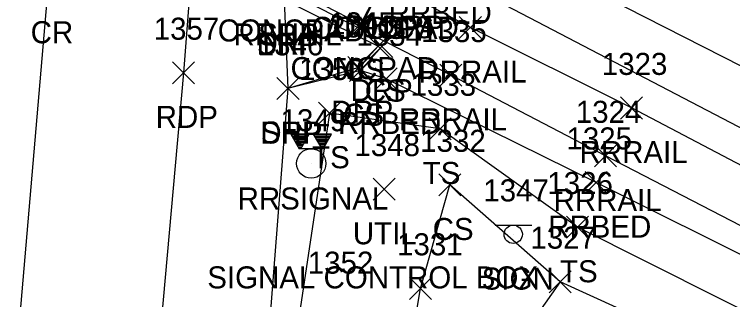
# Model space of a CAD drawing. Extents: x 1443960 to 1446865, y 610387 to 616706.
# Drawn here: x 1446594.4 to 1446659.6, y 611104.4 to 611130.2 of the extents above; entities that cross this region are included whole.
import ezdxf

# ---------------------------------------------------------------- set-up
doc = ezdxf.new("R2010")
doc.units = 0
for name, color, linetype in [('L_A', 7, 'Continuous'), ('L_I', 7, 'Continuous'), ('L_TIC', 7, 'Continuous'), ('LELB', 7, 'Continuous'), ('LS', 7, 'Continuous'), ('P_A', 7, 'Continuous'), ('P_I', 7, 'Continuous'), ('P_TIC', 7, 'Continuous'), ('PET', 7, 'Continuous'), ('PRC', 7, 'Continuous'), ('PSP', 7, 'Continuous'), ('R_A', 7, 'Continuous'), ('R_I', 7, 'Continuous'), ('R_TIC', 7, 'Continuous'), ('RDP', 7, 'Continuous'), ('RR', 7, 'Continuous'), ('RRB', 7, 'Continuous'), ('S_A', 7, 'Continuous'), ('S_I', 7, 'Continuous'), ('SSGN', 7, 'Continuous'), ('TCSH', 7, 'Continuous'), ('U_A', 7, 'Continuous'), ('U_C', 7, 'Continuous'), ('U_I', 7, 'Continuous'), ('UDEFAULT', 7, 'Continuous')]:
    doc.layers.add(name, color=color, linetype=linetype)

msp = doc.modelspace()

# ---------------------------------------------------------------- linework, layer by layer
at = {"layer": 'L_TIC'}
for points in [[(1446624.86, 611128.366), (1446626.86, 611130.366)], [(1446626.86, 611128.366), (1446624.86, 611130.366)], [(1446624.927, 611128.189), (1446626.927, 611130.189)], [(1446626.927, 611128.189), (1446624.927, 611130.189)], [(1446626.804, 611126.319), (1446628.804, 611128.319)], [(1446628.804, 611126.319), (1446626.804, 611128.319)], [(1446624.843, 611124.138), (1446626.843, 611126.138)], [(1446626.843, 611124.138), (1446624.843, 611126.138)], [(1446622.055, 611120.279), (1446624.055, 611122.279)], [(1446624.055, 611120.279), (1446622.055, 611122.279)], [(1446632.092, 611118.85), (1446634.092, 611120.85)], [(1446634.092, 611118.85), (1446632.092, 611120.85)], [(1446632.964, 611113.769), (1446634.964, 611115.769)], [(1446634.964, 611113.769), (1446632.964, 611115.769)], [(1446644.557, 611109.935), (1446646.557, 611111.935)], [(1446646.557, 611109.935), (1446644.557, 611111.935)], [(1446642.968, 611104.984), (1446644.968, 611106.984)], [(1446644.968, 611104.984), (1446642.968, 611106.984)], [(1446630.3, 611104.381), (1446632.3, 611106.381)], [(1446632.3, 611104.381), (1446630.3, 611106.381)]]:
    msp.add_lwpolyline(points, dxfattribs=at)
at = {"layer": 'LELB'}
for points in [[(1446646.009, 611451.428), (1446645.804, 611427.908), (1446642.941, 611384.684), (1446641.12, 611344.066), (1446637.897, 611299.181), (1446633.76, 611254.364), (1446628.531, 611208.76), (1446626.594, 611161.024), (1446631.891, 611151.516), (1446639.397, 611144.516), (1446638.888, 611137.349), (1446641.216, 611135.347), (1446691.88, 611109.533), (1446720.606, 611092.865), (1446765.351, 611070.855), (1446803.04, 611049.447), (1446832.291, 611033.435)], [(1446627.829, 611133.014), (1446625.927, 611129.189)], [(1446627.804, 611127.319), (1446625.843, 611125.138)], [(1446625.843, 611125.138), (1446619.275, 611123.52)], [(1446830.278, 611016.526), (1446811.095, 611028.659), (1446776.071, 611047.215), (1446765.101, 611052.744), (1446718.129, 611075.141), (1446677.696, 611094.8), (1446645.557, 611110.935), (1446633.092, 611119.85), (1446623.055, 611121.279), (1446619.751, 611099.299), (1446617.85, 611081.958), (1446615.601, 611043.859), (1446614.767, 611002.832), (1446608.037, 610951.597), (1446605.014, 610902.953), (1446601.472, 610861.356)], [(1446628.969, 611091.609), (1446631.3, 611105.381), (1446633.964, 611114.769)], [(1446643.968, 611105.984), (1446633.964, 611114.769)], [(1446829.253, 611014.381), (1446810.485, 611025.973), (1446776.258, 611044.05), (1446764.799, 611049.488), (1446716.623, 611070.841), (1446676.655, 611091.108), (1446643.968, 611105.984), (1446632.651, 611089.896), (1446628.969, 611091.609), (1446629.072, 611084.288), (1446632.066, 611081.466), (1446632.152, 611079.982), (1446631.665, 611078.241), (1446628.851, 611073.014), (1446626.956, 611043.36), (1446621.653, 611002.831), (1446619.789, 610952.718), (1446614.792, 610900.253), (1446612.135, 610862.121)]]:
    msp.add_lwpolyline(points, dxfattribs=at)
at = {"layer": 'LS'}
msp.add_lwpolyline([(1446627.754, 611133.018), (1446625.86, 611129.366), (1446619.252, 611132.78), (1446610.639, 611137.431), (1446598.292, 611143.458), (1446586.968, 611149.47), (1446576.857, 611154.593), (1446570.554, 611157.886)], dxfattribs=at)
at = {"layer": 'P_TIC'}
for points in [[(1446608.781, 611123.94), (1446610.781, 611125.94)], [(1446610.781, 611123.94), (1446608.781, 611125.94)], [(1446618.275, 611122.52), (1446620.275, 611124.52)], [(1446620.275, 611122.52), (1446618.275, 611124.52)]]:
    msp.add_lwpolyline(points, dxfattribs=at)
at = {"layer": 'PET'}
msp.add_lwpolyline([(1446610.706, 611136.75), (1446609.781, 611124.94), (1446606.079, 611083.403), (1446602.837, 611045.861), (1446594.91, 610952.221), (1446591.246, 610905.913), (1446588.265, 610860.887), (1446582.86, 610791.011), (1446578.03, 610732.6), (1446571.547, 610656.072), (1446565.598, 610584.231)], dxfattribs=at)
at = {"layer": 'PRC'}
msp.add_lwpolyline([(1446598.395, 611142.939), (1446597.487, 611132.619), (1446593.403, 611084.973), (1446589.915, 611047.691), (1446585, 610993.715), (1446580.73, 610956.896), (1446575.284, 610909.202), (1446570.191, 610861.522)], dxfattribs=at)
at = {"layer": 'PSP'}
msp.add_lwpolyline([(1446619.037, 611132.417), (1446618.926, 611131.582), (1446619.275, 611123.52), (1446616.011, 611082.042), (1446613.23, 611044.063), (1446609.789, 611002.89), (1446606.094, 610951.914), (1446601.783, 610903.978), (1446599.174, 610861.23), (1446593.055, 610789.594), (1446588.389, 610733.328), (1446581.302, 610654.531), (1446575.408, 610584.215)], dxfattribs=at)
at = {"layer": 'R_TIC'}
for points in [[(1446634.823, 611128.052), (1446636.823, 611130.052)], [(1446636.823, 611128.052), (1446634.823, 611130.052)], [(1446626.462, 611126.367), (1446628.462, 611128.367)], [(1446628.462, 611126.367), (1446626.462, 611128.367)], [(1446624.706, 611124.425), (1446626.706, 611126.425)], [(1446626.706, 611124.425), (1446624.706, 611126.425)], [(1446633.052, 611123.725), (1446635.052, 611125.725)], [(1446635.052, 611123.725), (1446633.052, 611125.725)], [(1446627.173, 611123.388), (1446629.173, 611125.388)], [(1446629.173, 611123.388), (1446627.173, 611125.388)], [(1446618.275, 611122.52), (1446620.275, 611124.52)], [(1446620.275, 611122.52), (1446618.275, 611124.52)], [(1446649.447, 611120.747), (1446651.447, 611122.747)], [(1446651.447, 611120.747), (1446649.447, 611122.747)], [(1446647.088, 611116.399), (1446649.088, 611118.399)], [(1446649.088, 611116.399), (1446647.088, 611118.399)], [(1446646.24, 611113.984), (1446648.24, 611115.984)], [(1446648.24, 611113.984), (1446646.24, 611115.984)]]:
    msp.add_lwpolyline(points, dxfattribs=at)
at = {"layer": 'RDP'}
msp.add_lwpolyline([(1446618.926, 611131.582), (1446627.462, 611127.367), (1446625.706, 611125.425), (1446619.275, 611123.52)], dxfattribs=at)
at = {"layer": 'RR'}
for points in [[(1446830.798, 611028.508), (1446813.796, 611037.339), (1446780.132, 611054.627), (1446766.604, 611061.724), (1446723.159, 611084.183), (1446681.833, 611105.5), (1446667.651, 611112.72), (1446650.447, 611121.747), (1446635.823, 611129.052), (1446620.356, 611137.272), (1446611.041, 611142.08), (1446598.972, 611148.352), (1446587.47, 611154.323), (1446577.265, 611159.614), (1446545.097, 611176.059), (1446537.945, 611179.668), (1446530.32, 611183.718), (1446472.23, 611213.591), (1446430.676, 611235.019), (1446393.224, 611254.187), (1446353.39, 611274.789), (1446345.668, 611278.801)], [(1446830.612, 611022.908), (1446812.005, 611032.725), (1446777.665, 611050.482), (1446764.895, 611057.052), (1446720.805, 611079.759), (1446679.612, 611101.042), (1446672.595, 611104.746), (1446648.088, 611117.399), (1446634.052, 611124.725), (1446619.037, 611132.417), (1446610.706, 611136.75), (1446598.395, 611142.939), (1446586.963, 611148.928), (1446576.92, 611154.083), (1446541.415, 611172.478), (1446511.363, 611187.889), (1446469.876, 611209.21), (1446428.536, 611230.416), (1446391.04, 611249.762), (1446351.07, 611270.343), (1446343.043, 611274.543)]]:
    msp.add_lwpolyline(points, dxfattribs=at)
at = {"layer": 'RRB'}
for points in [[(1446632.764, 611134.379), (1446690.22, 611104.365), (1446720.363, 611090.64), (1446766.523, 611065.079), (1446801.875, 611047.122), (1446831.426, 611030.908)], [(1446628.173, 611124.388), (1446625.843, 611125.138)], [(1446831.592, 611019.772), (1446811.473, 611030.772), (1446776.478, 611048.395), (1446764.372, 611054.869), (1446719.702, 611077.579), (1446678.829, 611099.241), (1446647.24, 611114.984), (1446628.173, 611124.388)]]:
    msp.add_lwpolyline(points, dxfattribs=at)
at = {"layer": 'SSGN'}
for p, q in [((1446638.066, 611111.122), (1446641.4, 611111.122)), ((1446639.713, 611110.288), (1446639.713, 611110.288))]:
    msp.add_line(p, q, dxfattribs=at)
msp.add_circle((1446639.713, 611110.288), 0.833, dxfattribs=at)
at = {"layer": 'TCSH'}
for p, q in [((1446621.198, 611119.38), (1446619.531, 611119.38)), ((1446619.531, 611119.38), (1446620.301, 611118.047)), ((1446620.428, 611118.047), (1446621.198, 611119.38)), ((1446623.232, 611119.38), (1446621.565, 611119.38)), ((1446621.565, 611119.38), (1446622.335, 611118.047)), ((1446622.462, 611118.047), (1446623.232, 611119.38)), ((1446622.462, 611118.047), (1446620.301, 611118.047)), ((1446621.382, 611116.713), (1446621.382, 611116.713))]:
    msp.add_line(p, q, dxfattribs=at)
for points in [[(1446619.575, 611119.304), (1446621.153, 611119.304)], [(1446619.652, 611119.17), (1446621.076, 611119.17)], [(1446619.729, 611119.037), (1446620.999, 611119.037)], [(1446621.593, 611119.332), (1446623.204, 611119.332)], [(1446621.67, 611119.199), (1446623.127, 611119.199)], [(1446621.747, 611119.065), (1446623.05, 611119.065)], [(1446619.806, 611118.904), (1446620.922, 611118.904)], [(1446619.883, 611118.77), (1446620.845, 611118.77)], [(1446619.96, 611118.637), (1446620.768, 611118.637)], [(1446620.037, 611118.504), (1446620.691, 611118.504)], [(1446620.114, 611118.37), (1446620.615, 611118.37)], [(1446621.824, 611118.932), (1446622.973, 611118.932)], [(1446621.901, 611118.799), (1446622.896, 611118.799)], [(1446621.978, 611118.665), (1446622.819, 611118.665)], [(1446622.055, 611118.532), (1446622.742, 611118.532)], [(1446622.132, 611118.399), (1446622.665, 611118.399)], [(1446620.191, 611118.237), (1446620.538, 611118.237)], [(1446620.268, 611118.104), (1446620.461, 611118.104)], [(1446622.209, 611118.265), (1446622.588, 611118.265)], [(1446622.286, 611118.132), (1446622.511, 611118.132)]]:
    msp.add_lwpolyline(points, dxfattribs=at)
msp.add_circle((1446621.382, 611116.713), 1.333, dxfattribs=at)
at = {"layer": 'UDEFAULT'}
for points in [[(1446626.997, 611113.379), (1446628.997, 611115.379)], [(1446628.997, 611113.379), (1446626.997, 611115.379)]]:
    msp.add_lwpolyline(points, dxfattribs=at)

# ---------------------------------------------------------------- texts
at = {"layer": 'L_A'}
for s, p in [('CS', (1446628.795, 611128.072)), ('CONCPAD', (1446612.898, 611127.78)), ('CONCPAD', (1446621.4, 611128.018)), ('CONCPAD', (1446621.4, 611128.018)), ('CS', (1446626.27, 611128.014)), ('CONCPAD', (1446619.506, 611124.366)), ('CS', (1446624.368, 611124.189)), ('CS', (1446626.245, 611122.319)), ('CS', (1446624.284, 611120.138)), ('TS', (1446621.464, 611116.279)), ('TS', (1446631.501, 611114.85)), ('CS', (1446632.405, 611109.769)), ('TS', (1446643.966, 611105.935))]:
    msp.add_text(s, height=2, dxfattribs=at).set_placement(p)
at = {"layer": 'L_I'}
for s, p in [('2001', (1446622.993, 611128.138)), ('1350', (1446620.275, 611124.279)), ('1333', (1446630.399, 611122.85)), ('1332', (1446631.271, 611117.769)), ('1326', (1446642.809, 611113.935)), ('1327', (1446641.275, 611108.984)), ('1331', (1446629.174, 611108.381))]:
    msp.add_text(s, height=2, dxfattribs=at).set_placement(p)
at = {"layer": 'P_A'}
for s, p in [('CR', (1446595.92, 611127.619)), ('SHP', (1446616.572, 611127.417)), ('SHP', (1446616.461, 611126.582)), ('RDP', (1446607.27, 611119.94)), ('SHP', (1446616.81, 611118.52))]:
    msp.add_text(s, height=2, dxfattribs=at).set_placement(p)
at = {"layer": 'P_I'}
for s, p in [('1357', (1446607.089, 611127.94)), ('1346', (1446616.527, 611126.52))]:
    msp.add_text(s, height=2, dxfattribs=at).set_placement(p)
at = {"layer": 'R_A'}
for s, p in [('RRBED', (1446628.409, 611129.379)), ('DRP', (1446627.795, 611128.124)), ('RRRAIL', (1446614.328, 611127.417)), ('DRP', (1446616.414, 611126.582)), ('RRRAIL', (1446631.114, 611124.052)), ('DRP', (1446624.951, 611122.367)), ('DRP', (1446623.194, 611120.425)), ('RRRAIL', (1446629.344, 611119.725)), ('RRBED', (1446623.819, 611119.388)), ('DRP', (1446616.763, 611118.52)), ('RRRAIL', (1446645.739, 611116.747)), ('RRSIGNAL', (1446614.708, 611112.536)), ('RRRAIL', (1446643.38, 611112.399)), ('RRBED', (1446642.886, 611109.984))]:
    msp.add_text(s, height=2, dxfattribs=at).set_placement(p)
at = {"layer": 'R_I'}
for s, p in [('1345', (1446623.013, 611128.425)), ('1334', (1446625.481, 611127.388)), ('1335', (1446631.36, 611127.725)), ('1346', (1446616.527, 611126.52)), ('1323', (1446647.755, 611124.747)), ('1324', (1446645.395, 611120.399)), ('1349', (1446618.606, 611119.636)), ('1325', (1446644.547, 611117.984))]:
    msp.add_text(s, height=2, dxfattribs=at).set_placement(p)
at = {"layer": 'S_A'}
msp.add_text('SIGN', height=2, dxfattribs=at).set_placement((1446636.851, 611105.268))
at = {"layer": 'S_I'}
for s, p in [('1347', (1446637.001, 611113.268)), ('1352', (1446621.072, 611106.715))]:
    msp.add_text(s, height=2, dxfattribs=at).set_placement(p)
at = {"layer": 'U_A'}
msp.add_text('UTIL', height=2, dxfattribs=at).set_placement((1446625.162, 611109.379))
at = {"layer": 'U_C'}
msp.add_text('SIGNAL CONTROL BOX', height=2, dxfattribs=at).set_placement((1446611.95, 611105.379))
at = {"layer": 'U_I'}
msp.add_text('1348', height=2, dxfattribs=at).set_placement((1446625.304, 611117.379))

doc.saveas('drawing.dxf')
